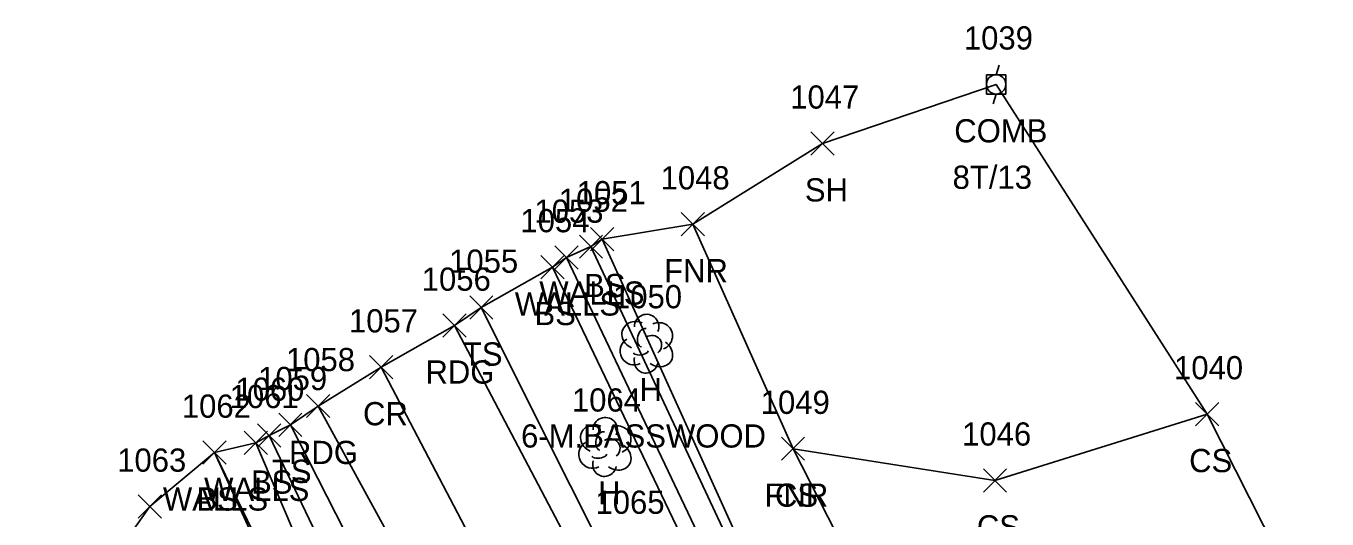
# Model space of a CAD drawing. Extents: x 1441651 to 1442140, y 243798 to 245625.
# Drawn here: x 1441912.8 to 1442024.9, y 245582.1 to 245624.6 of the extents above; entities that cross this region are included whole.
import ezdxf

# ---------------------------------------------------------------- set-up
doc = ezdxf.new("R2010")
doc.units = 0
for name, color, linetype in [('L_A', 7, 'Continuous'), ('L_C', 7, 'Continuous'), ('L_I', 7, 'Continuous'), ('L_TIC', 7, 'Continuous'), ('LELB', 7, 'Continuous'), ('LFNC', 7, 'Continuous'), ('LSOGP', 7, 'Continuous'), ('LTD', 7, 'Continuous'), ('LWS', 7, 'Continuous'), ('P_A', 7, 'Continuous'), ('P_I', 7, 'Continuous'), ('P_TIC', 7, 'Continuous'), ('PEU', 7, 'Continuous'), ('PRC', 7, 'Continuous'), ('U_A', 7, 'Continuous'), ('U_C', 7, 'Continuous'), ('U_I', 7, 'Continuous'), ('UP', 7, 'Continuous')]:
    doc.layers.add(name, color=color, linetype=linetype)

msp = doc.modelspace()

# ---------------------------------------------------------------- linework, layer by layer
at = {"layer": 'L_TIC'}
for points in [[(1441980.39, 245613.5), (1441982.39, 245615.5)], [(1441982.39, 245613.5), (1441980.39, 245615.5)], [(1441969.22, 245606.54), (1441971.22, 245608.54)], [(1441971.22, 245606.54), (1441969.22, 245608.54)], [(1441961.42, 245605.26), (1441963.42, 245607.26)], [(1441963.42, 245605.26), (1441961.42, 245607.26)], [(1441960.45, 245604.61), (1441962.45, 245606.61)], [(1441962.45, 245604.61), (1441960.45, 245606.61)], [(1441957.14, 245602.85), (1441959.14, 245604.85)], [(1441959.14, 245602.85), (1441957.14, 245604.85)], [(1441958.35, 245603.67), (1441960.35, 245605.67)], [(1441960.35, 245603.67), (1441958.35, 245605.67)], [(1441951, 245599.36), (1441953, 245601.36)], [(1441953, 245599.36), (1441951, 245601.36)], [(1441934.55, 245589.25), (1441936.55, 245591.25)], [(1441936.55, 245589.25), (1441934.55, 245591.25)], [(1442013.55, 245590.18), (1442015.55, 245592.18)], [(1442015.55, 245590.18), (1442013.55, 245592.18)], [(1441932.72, 245588.33), (1441934.72, 245590.33)], [(1441934.72, 245588.33), (1441932.72, 245590.33)], [(1441931.57, 245587.7), (1441933.57, 245589.7)], [(1441933.57, 245587.7), (1441931.57, 245589.7)], [(1441977.86, 245587.2), (1441979.86, 245589.2)], [(1441979.86, 245587.2), (1441977.86, 245589.2)], [(1441977.86, 245587.2), (1441979.86, 245589.2)], [(1441979.86, 245587.2), (1441977.86, 245589.2)], [(1441928.02, 245586.87), (1441930.02, 245588.87)], [(1441930.02, 245586.87), (1441928.02, 245588.87)], [(1441928.02, 245586.87), (1441930.02, 245588.87)], [(1441930.02, 245586.87), (1441928.02, 245588.87)], [(1441995.26, 245584.47), (1441997.26, 245586.47)], [(1441997.26, 245584.47), (1441995.26, 245586.47)], [(1441922.45, 245582.22), (1441924.45, 245584.22)], [(1441924.45, 245582.22), (1441922.45, 245584.22)]]:
    msp.add_lwpolyline(points, dxfattribs=at)
at = {"layer": 'LELB'}
for points in [[(1441962.42, 245606.26), (1441976.58, 245575), (1441991.36, 245547.34), (1442006.24, 245518.42), (1442001.28, 245515.81)], [(1441958.14, 245603.85), (1441973.05, 245572.7), (1441987.15, 245544.68), (1442001.28, 245515.81), (1442017.22, 245492.13), (1442028.73, 245467.17), (1442040.19, 245452.02), (1442046.6, 245443.33), (1442055.54, 245439.06), (1442059.34, 245437.76)], [(1441952, 245600.36), (1441967.38, 245569.64), (1441982.75, 245542), (1441998.18, 245514.4), (1442013.67, 245490.09), (1442025.65, 245464.6), (1442043.56, 245442.55), (1442056.06, 245427.98)], [(1442014.55, 245591.18), (1441996.26, 245585.47), (1441978.86, 245588.2)], [(1441935.55, 245590.25), (1441950.41, 245561.12), (1441965.85, 245535.51), (1441982.29, 245505.63), (1441993.22, 245488.68)], [(1441933.72, 245589.33), (1441948.49, 245558.46), (1441956.21, 245536.7), (1441975.05, 245500.1), (1441979.33, 245493.09), (1441987.53, 245478.54), (1441986.56, 245474.39), (1441981.27, 245469.98), (1441969.1, 245476.16)], [(1441929.02, 245587.87), (1441942.94, 245557.34), (1441953.32, 245535.96), (1441954.96, 245536.46), (1441956.21, 245536.7)], [(1441923.45, 245583.22), (1441912.77, 245568.1), (1441914.39, 245547.71), (1441930.79, 245525.13), (1441946.54, 245502.48), (1441950.68, 245491.32), (1441947.35, 245479.46), (1441950.83, 245463.21), (1441954.45, 245457.19), (1441962.21, 245455.42), (1441972.58, 245437.76), (1441995.95, 245413.46), (1442007.46, 245408.08), (1442021.35, 245397.08), (1442029.3, 245403.17), (1442035.63, 245410.33), (1442039.93, 245412.91), (1442042.78, 245414.27)]]:
    msp.add_lwpolyline(points, dxfattribs=at)
at = {"layer": 'LFNC'}
msp.add_lwpolyline([(1441970.22, 245607.54), (1441978.86, 245588.2), (1441995.27, 245556.04), (1442014.76, 245516.33), (1442024.69, 245495.45), (1442031.67, 245481.04), (1442036.99, 245470.06), (1442042.58, 245457.76), (1442044.09, 245455.72)], dxfattribs=at)
at = {"layer": 'LSOGP'}
msp.add_lwpolyline([(1442030.34, 245559.96), (1442014.55, 245591.18), (1441996.36, 245619.59), (1441981.39, 245614.5), (1441970.22, 245607.54), (1441962.42, 245606.26), (1441961.45, 245605.61), (1441959.35, 245604.67), (1441958.14, 245603.85), (1441952, 245600.36), (1441949.7, 245598.81), (1441943.37, 245595.22), (1441937.94, 245591.88), (1441935.55, 245590.25), (1441933.72, 245589.33), (1441932.57, 245588.7), (1441929.02, 245587.87), (1441923.45, 245583.22), (1441912.77, 245568.1)], dxfattribs=at)
at = {"layer": 'LTD'}
for p, q in [((1441966.21, 245597.3), (1441966.21, 245597.3)), ((1441966.21, 245597.3), (1441966.21, 245597.3)), ((1441962.63, 245588.4), (1441962.63, 245588.4)), ((1441962.63, 245588.4), (1441962.63, 245588.4))]:
    msp.add_line(p, q, dxfattribs=at)
for centre in [(1441966.25, 245598.73), (1441962.68, 245589.84)]:
    msp.add_arc(centre, 1.05, 335.5272, 180.9563, dxfattribs=at)
for centre, major_axis, ratio, start_param, end_param in [((1441965.41, 245597.97), (1.21, -0.51), 0.895232, 1.570796, 4.712389), ((1441967.25, 245597.88), (-1.14, -0.48), 0.949671, 1.570796, 4.712389), ((1441966, 245597.76), (-0.208, -0.792), 0.645439, 3.141593, 6.283185), ((1441966.71, 245597.13), (-0.5, 0.667), 0.989748, 3.141593, 6.283185), ((1441965.12, 245596.59), (0.58, -1.04), 0.959034, 3.141593, 6.283185), ((1441967.21, 245596.47), (-1.09, 0.79), 0.841452, 1.570796, 4.712389), ((1441966.21, 245595.8), (0.26, 1.06), 0.942809, 1.570796, 4.712389), ((1441965.75, 245596.55), (-0.625, -0.083), 0.423636, 0, 3.141593), ((1441961.84, 245589.07), (1.21, -0.51), 0.895232, 1.570796, 4.712389), ((1441963.67, 245588.99), (-1.14, -0.48), 0.949671, 1.570796, 4.712389), ((1441962.42, 245588.86), (-0.208, -0.792), 0.645439, 3.141593, 6.283185), ((1441963.13, 245588.24), (-0.5, 0.667), 0.989748, 3.141593, 6.283185), ((1441961.55, 245587.69), (0.58, -1.04), 0.959034, 3.141593, 6.283185), ((1441963.63, 245587.57), (-1.09, 0.79), 0.841452, 1.570796, 4.712389), ((1441962.63, 245586.9), (0.26, 1.06), 0.942809, 1.570796, 4.712389), ((1441962.17, 245587.65), (-0.625, -0.083), 0.423636, 0, 3.141593)]:
    msp.add_ellipse(centre, major_axis=major_axis, ratio=ratio, start_param=start_param, end_param=end_param, dxfattribs=at)
at = {"layer": 'LWS'}
for points in [[(1441959.35, 245604.67), (1441974.31, 245573.24), (1441988.02, 245544.83), (1442001.28, 245518.1), (1442004.3, 245519.09)], [(1441961.45, 245605.61), (1441976.15, 245574.21), (1441990.78, 245546.65), (1442004.3, 245519.09)], [(1441929.02, 245587.87), (1441943.67, 245557.7), (1441954.05, 245536.93), (1441955.19, 245537.55)], [(1441932.57, 245588.7), (1441945.41, 245558.54), (1441955.19, 245537.55)]]:
    msp.add_lwpolyline(points, dxfattribs=at)
at = {"layer": 'P_TIC'}
for points in [[(1441948.7, 245597.81), (1441950.7, 245599.81)], [(1441950.7, 245597.81), (1441948.7, 245599.81)], [(1441942.37, 245594.22), (1441944.37, 245596.22)], [(1441944.37, 245594.22), (1441942.37, 245596.22)], [(1441936.94, 245590.88), (1441938.94, 245592.88)], [(1441938.94, 245590.88), (1441936.94, 245592.88)]]:
    msp.add_lwpolyline(points, dxfattribs=at)
at = {"layer": 'PEU'}
for points in [[(1441949.7, 245598.81), (1441965.58, 245568.64), (1441979.81, 245540.54), (1441994.5, 245512.77), (1442011.02, 245488.25), (1442024.85, 245464.87), (1442045.34, 245434.3), (1442053.64, 245424.38)], [(1441937.94, 245591.88), (1441953.89, 245562.72), (1441968.91, 245535.69), (1441984.8, 245506.98), (1441992.99, 245492.3), (1442013.08, 245458.97), (1442024.73, 245444.52), (1442043.13, 245414.63), (1442048.27, 245419.3), (1442053.64, 245424.38)]]:
    msp.add_lwpolyline(points, dxfattribs=at)
at = {"layer": 'PRC'}
msp.add_lwpolyline([(1441943.37, 245595.22), (1441959.06, 245565.31), (1441973.71, 245538.05), (1441989.92, 245509.63), (1442005.51, 245485.14), (1442020.38, 245462.65), (1442040.92, 245430.94), (1442048.27, 245419.3)], dxfattribs=at)
at = {"layer": 'UP'}
for p, q in [((1441995.53, 245618.75), (1441995.53, 245620.42)), ((1441995.53, 245620.42), (1441997.19, 245620.42)), ((1441996.61, 245621.25), (1441996.36, 245620.42)), ((1441997.19, 245620.42), (1441997.19, 245618.75)), ((1441996.36, 245619.59), (1441996.36, 245619.59)), ((1441997.19, 245618.75), (1441995.53, 245618.75)), ((1441996.11, 245617.92), (1441996.36, 245618.75))]:
    msp.add_line(p, q, dxfattribs=at)
msp.add_circle((1441996.36, 245619.59), 0.833, dxfattribs=at)

# ---------------------------------------------------------------- texts
at = {"layer": 'L_A'}
for s, p in [('SH', (1441979.88, 245609.5)), ('FNR', (1441967.75, 245602.54)), ('WALLS', (1441957, 245600.61)), ('BS', (1441960.86, 245601.26)), ('WALLS', (1441954.89, 245599.67)), ('BS', (1441956.58, 245598.85)), ('TS', (1441950.41, 245595.36)), ('H', (1441965.64, 245592.3)), ('CS', (1442012.99, 245586.18)), ('TS', (1441933.96, 245585.25)), ('WALLS', (1441928.12, 245583.7)), ('BS', (1441932.16, 245584.33)), ('WALLS', (1441924.57, 245582.87)), ('BS', (1441927.46, 245582.87)), ('H', (1441962.07, 245583.4)), ('FNR', (1441976.4, 245583.2)), ('CS', (1441977.3, 245583.2)), ('CS', (1441994.7, 245580.47))]:
    msp.add_text(s, height=2, dxfattribs=at).set_placement(p)
at = {"layer": 'L_C'}
msp.add_text('6-M.BASSWOOD', height=2, dxfattribs=at).set_placement((1441955.43, 245588.3))
at = {"layer": 'L_I'}
for s, p in [('1047', (1441978.62, 245617.5)), ('1048', (1441967.45, 245610.54)), ('1052', (1441958.68, 245608.61)), ('1051', (1441960.22, 245609.26)), ('1053', (1441956.58, 245607.67)), ('1054', (1441955.37, 245606.85)), ('1055', (1441949.23, 245603.36)), ('1050', (1441963.35, 245600.3)), ('1040', (1442011.69, 245594.18)), ('1059', (1441932.77, 245593.25)), ('1061', (1441930.32, 245591.7)), ('1060', (1441930.81, 245592.33)), ('1064', (1441959.81, 245591.4)), ('1062', (1441926.2, 245590.87)), ('1062', (1441926.2, 245590.87)), ('1049', (1441976.08, 245591.2)), ('1049', (1441976.08, 245591.2)), ('1046', (1441993.43, 245588.47)), ('1063', (1441920.63, 245586.22)), ('1065', (1441961.84, 245582.59))]:
    msp.add_text(s, height=2, dxfattribs=at).set_placement(p)
at = {"layer": 'P_A'}
for s, p in [('RDG', (1441947.19, 245593.81)), ('CR', (1441941.81, 245590.22)), ('RDG', (1441935.43, 245586.88))]:
    msp.add_text(s, height=2, dxfattribs=at).set_placement(p)
at = {"layer": 'P_I'}
for s, p in [('1056', (1441946.87, 245601.81)), ('1057', (1441940.6, 245598.22)), ('1058', (1441935.17, 245594.88))]:
    msp.add_text(s, height=2, dxfattribs=at).set_placement(p)
at = {"layer": 'U_A'}
msp.add_text('COMB', height=2, dxfattribs=at).set_placement((1441992.75, 245614.59))
at = {"layer": 'U_C'}
msp.add_text('8T/13', height=2, dxfattribs=at).set_placement((1441992.61, 245610.59))
at = {"layer": 'U_I'}
msp.add_text('1039', height=2, dxfattribs=at).set_placement((1441993.58, 245622.59))

doc.saveas('drawing.dxf')
